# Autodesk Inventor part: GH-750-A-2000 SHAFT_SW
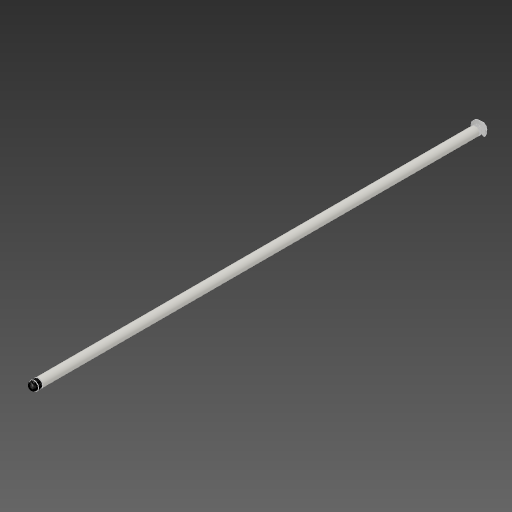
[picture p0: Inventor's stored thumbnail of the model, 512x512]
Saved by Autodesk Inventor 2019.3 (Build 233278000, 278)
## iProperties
Created: 2018-11
Part Number: GH-750-A-2000 SHAFT_SW
Material: Generic
Document SubType Name: Modeling
Designer: Justin
Density: 1 g/cm^3
Appearance: Default
Author: Justin
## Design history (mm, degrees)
node "Assembly1" dims "d0" = 10
body "Solid1"
node "Part1:1" dims "d0" = 10
node "Part2:1" dims "d0" = 10
body "Solid2"
node "Part3:1" dims "d0" = 10
body "Solid3"
